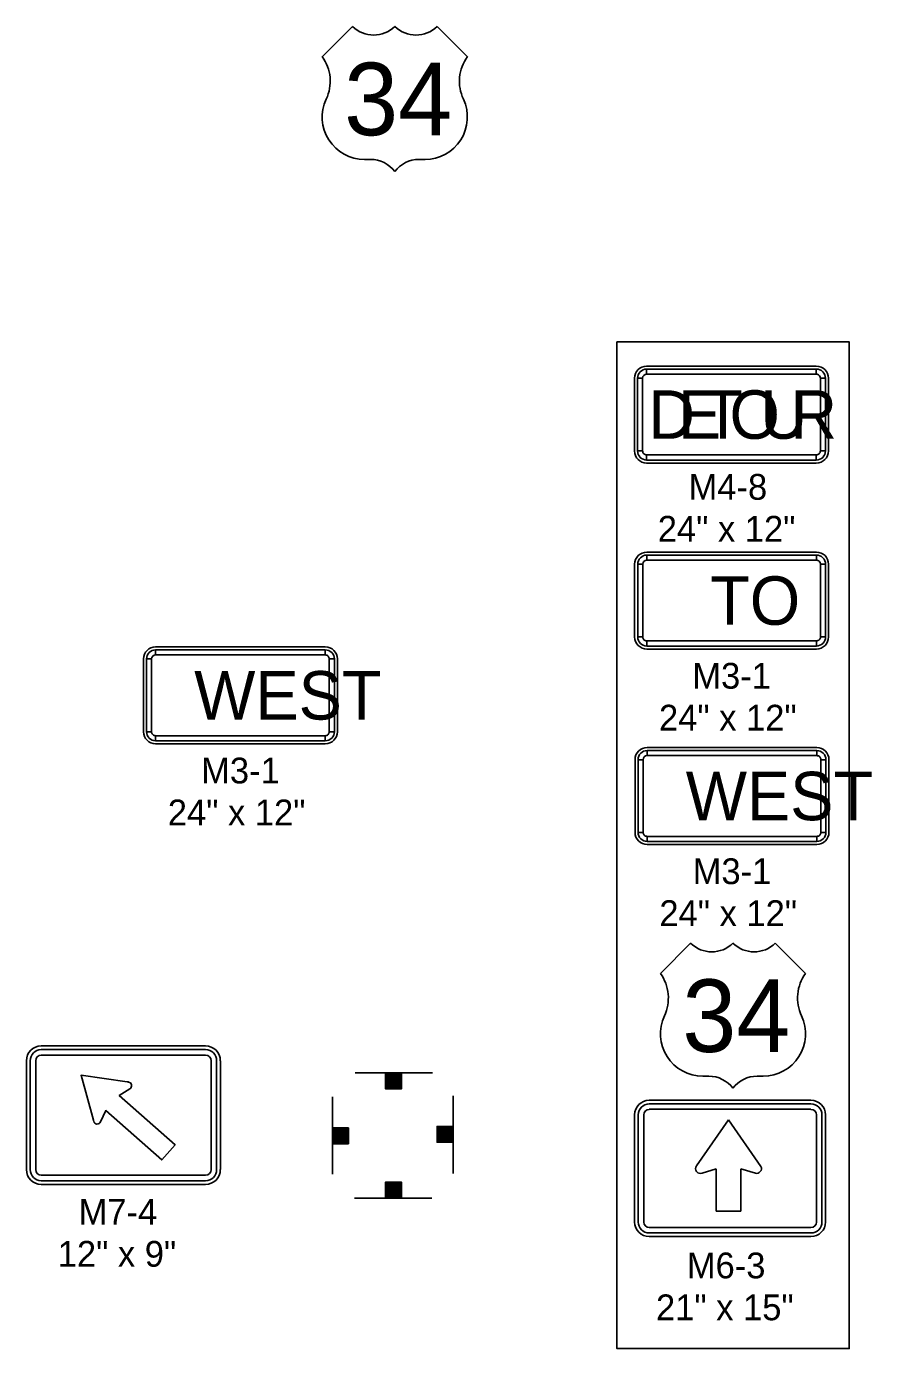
# Model space of a CAD drawing. Extents: x 10133 to 81668, y 6132 to 11018.
# Drawn here: x 11270.8 to 11532.9, y 6709.2 to 7119.3 of the extents above; entities that cross this region are included whole.
import ezdxf

# ---------------------------------------------------------------- set-up
doc = ezdxf.new("R2010")
doc.units = 0
for name, color, linetype in [('dsnTextFinalPlan', 7, 'Continuous'), ('Level 10', 7, 'Continuous'), ('Level 4', 7, 'Continuous'), ('Level 5', 7, 'Continuous')]:
    doc.layers.add(name, color=color, linetype=linetype)

msp = doc.modelspace()

# ---------------------------------------------------------------- linework, layer by layer
at = {"layer": 'dsnTextFinalPlan'}
for p, q in [((11326.33, 6803.08), (11275.37, 6803.08)), ((11270.79, 6798.5), (11270.79, 6764.72)), ((11330.92, 6764.72), (11330.92, 6798.5)), ((11372.68, 6794.77), (11396.68, 6794.77)), ((11387.04, 6794.41), (11382.16, 6794.41)), ((11382.16, 6794.16), (11387.04, 6794.16)), ((11387.04, 6793.94), (11382.16, 6793.94)), ((11382.16, 6793.71), (11387.04, 6793.71)), ((11387.04, 6793.51), (11382.16, 6793.51)), ((11382.16, 6793.33), (11387.04, 6793.33)), ((11387.04, 6793.04), (11382.16, 6793.04)), ((11382.16, 6792.81), (11387.04, 6792.81)), ((11387.04, 6792.61), (11382.16, 6792.63)), ((11382.16, 6792.33), (11387.04, 6792.33)), ((11387.04, 6792), (11382.16, 6792)), ((11382.16, 6791.63), (11387.04, 6791.63)), ((11387.04, 6791.43), (11382.16, 6791.45)), ((11382.16, 6791.07), (11387.04, 6791.06)), ((11387.04, 6790.87), (11382.16, 6790.87)), ((11365.65, 6763.31), (11365.65, 6787.31)), ((11382.16, 6790.6), (11387.04, 6790.6)), ((11387.04, 6790.4), (11382.16, 6790.4)), ((11382.16, 6790.12), (11387.04, 6790.12)), ((11403.13, 6787.57), (11403.13, 6763.57)), ((11366.01, 6777.66), (11366.01, 6772.79)), ((11366.25, 6772.79), (11366.25, 6777.66)), ((11366.48, 6777.66), (11366.48, 6772.79)), ((11366.71, 6772.79), (11366.71, 6777.66)), ((11366.91, 6777.66), (11366.91, 6772.79)), ((11367.09, 6772.79), (11367.09, 6777.66)), ((11367.38, 6777.66), (11367.38, 6772.79)), ((11367.61, 6772.79), (11367.61, 6777.66)), ((11367.81, 6777.66), (11367.79, 6772.79)), ((11368.09, 6772.79), (11368.09, 6777.66)), ((11368.41, 6777.66), (11368.41, 6772.79)), ((11368.79, 6772.79), (11368.79, 6777.66)), ((11368.99, 6777.66), (11368.97, 6772.79)), ((11369.35, 6772.79), (11369.36, 6777.66)), ((11369.54, 6777.66), (11369.54, 6772.79)), ((11369.82, 6772.79), (11369.82, 6777.66)), ((11370.02, 6777.66), (11370.02, 6772.79)), ((11370.29, 6772.79), (11370.29, 6777.66)), ((11398.48, 6778.09), (11398.48, 6773.22)), ((11398.76, 6773.22), (11398.76, 6778.09)), ((11398.95, 6778.09), (11398.95, 6773.22)), ((11399.23, 6773.22), (11399.23, 6778.09)), ((11399.43, 6778.09), (11399.41, 6773.22)), ((11399.79, 6773.22), (11399.81, 6778.09)), ((11399.99, 6778.09), (11399.99, 6773.22)), ((11400.36, 6773.22), (11400.36, 6778.09)), ((11400.69, 6778.09), (11400.69, 6773.22)), ((11400.97, 6773.22), (11400.98, 6778.09)), ((11401.16, 6778.09), (11401.16, 6773.22)), ((11401.39, 6773.22), (11401.39, 6778.09)), ((11401.69, 6778.09), (11401.69, 6773.22)), ((11401.87, 6773.22), (11401.87, 6778.09)), ((11402.06, 6778.09), (11402.06, 6773.22)), ((11402.29, 6773.22), (11402.29, 6778.09)), ((11402.52, 6778.09), (11402.52, 6773.22)), ((11402.77, 6773.22), (11402.77, 6778.09)), ((11275.37, 6760.13), (11326.33, 6760.13)), ((11387.02, 6760.54), (11382.14, 6760.54)), ((11382.14, 6760.26), (11387.02, 6760.26)), ((11387.02, 6760.06), (11382.14, 6760.06)), ((11382.14, 6759.78), (11387.02, 6759.78)), ((11387.02, 6759.59), (11382.14, 6759.6)), ((11382.14, 6759.23), (11387.02, 6759.21)), ((11387.02, 6759.03), (11382.14, 6759.03)), ((11382.14, 6758.65), (11387.02, 6758.65)), ((11387.02, 6758.33), (11382.14, 6758.33)), ((11382.14, 6758.05), (11387.02, 6758.03)), ((11396.5, 6755.89), (11372.5, 6755.89)), ((11387.02, 6757.85), (11382.14, 6757.85)), ((11382.14, 6757.62), (11387.02, 6757.62)), ((11387.02, 6757.33), (11382.14, 6757.33)), ((11382.14, 6757.15), (11387.02, 6757.15)), ((11387.02, 6756.95), (11382.14, 6756.95)), ((11382.14, 6756.72), (11387.02, 6756.72)), ((11387.02, 6756.49), (11382.14, 6756.49)), ((11382.14, 6756.25), (11387.02, 6756.25))]:
    msp.add_line(p, q, dxfattribs=at)
for points in [[(11453.89, 7021.45), (11525.96, 7021.45), (11525.96, 6709.23), (11453.89, 6709.23)], [(11387.04, 6794.69), (11382.13, 6794.69), (11382.13, 6789.78), (11387.04, 6789.78)], [(11365.73, 6777.66), (11365.73, 6772.75), (11370.64, 6772.75), (11370.64, 6777.66)], [(11403.05, 6773.22), (11403.05, 6778.13), (11398.14, 6778.13), (11398.14, 6773.22)], [(11382.14, 6755.97), (11387.05, 6755.97), (11387.05, 6760.88), (11382.14, 6760.88)]]:
    msp.add_lwpolyline(points, close=True, dxfattribs=at)
for points in [[(11302.07, 6791.95), (11287.71, 6794.02), (11291.56, 6780.04)], [(11293.78, 6779.52), (11295.4, 6783.04), (11312.73, 6767.75), (11316.88, 6772.46), (11299.56, 6787.75), (11302.85, 6789.78)]]:
    msp.add_lwpolyline(points, dxfattribs=at)
for centre, radius, start, end in [((11275.37, 6798.5), 4.58, 90, 180), ((11326.33, 6798.5), 4.58, 360, 90), ((11318.6, 6906.73), 115.96, 261.8049, 261.9654), ((11302.23, 6790.75), 1.16, 302.6073, 81.9654), ((11179.78, 6749.18), 115.96, 15.2659, 15.4333), ((11292.75, 6780.01), 1.14, 195.2659, 334.5454), ((11275.37, 6764.72), 4.58, 180, 270), ((11326.33, 6764.72), 4.58, 270, 0)]:
    msp.add_arc(centre, radius, start, end, dxfattribs=at)
at = {"layer": 'Level 10'}
for p, q in [((11463.1, 7013.94), (11515.72, 7013.94)), ((11463.1, 7011.44), (11463.1, 7013)), ((11515.72, 7013), (11515.72, 7011.44)), ((11459.34, 6987.64), (11459.34, 7010.19)), ((11460.28, 7010.19), (11461.85, 7010.19)), ((11516.97, 7010.19), (11518.53, 7010.19)), ((11519.47, 7010.19), (11519.47, 6987.64)), ((11461.85, 6987.64), (11460.28, 6987.64)), ((11518.53, 6987.64), (11516.97, 6987.64)), ((11463.1, 6984.82), (11463.1, 6986.39)), ((11515.72, 6983.88), (11463.1, 6983.88)), ((11515.72, 6986.39), (11515.72, 6984.82)), ((11463.15, 6956.26), (11515.76, 6956.26)), ((11463.15, 6953.75), (11463.15, 6955.32)), ((11515.76, 6955.32), (11515.76, 6953.75)), ((11459.39, 6929.95), (11459.39, 6952.5)), ((11460.33, 6952.5), (11461.9, 6952.5)), ((11517.01, 6952.5), (11518.58, 6952.5)), ((11519.52, 6952.5), (11519.52, 6929.95)), ((11310.84, 6926.87), (11363.45, 6926.87)), ((11461.9, 6929.95), (11460.33, 6929.95)), ((11463.15, 6927.13), (11463.15, 6928.7)), ((11515.76, 6926.19), (11463.15, 6926.19)), ((11515.76, 6928.7), (11515.76, 6927.13)), ((11518.58, 6929.95), (11517.01, 6929.95)), ((11307.08, 6900.56), (11307.08, 6923.11)), ((11308.02, 6923.11), (11309.58, 6923.11)), ((11310.84, 6924.36), (11310.84, 6925.93)), ((11363.45, 6925.93), (11363.45, 6924.36)), ((11364.7, 6923.11), (11366.27, 6923.11)), ((11367.21, 6923.11), (11367.21, 6900.56)), ((11309.58, 6900.56), (11308.02, 6900.56)), ((11310.84, 6897.74), (11310.84, 6899.31)), ((11363.45, 6899.31), (11363.45, 6897.74)), ((11366.27, 6900.56), (11364.7, 6900.56)), ((11363.45, 6896.8), (11310.84, 6896.8)), ((11463.27, 6895.64), (11515.88, 6895.64)), ((11463.27, 6893.14), (11463.27, 6894.7)), ((11515.88, 6894.7), (11515.88, 6893.14)), ((11459.51, 6869.33), (11459.51, 6891.88)), ((11460.45, 6891.88), (11462.01, 6891.88)), ((11517.13, 6891.88), (11518.7, 6891.88)), ((11519.64, 6891.88), (11519.64, 6869.33)), ((11462.01, 6869.33), (11460.45, 6869.33)), ((11518.7, 6869.33), (11517.13, 6869.33)), ((11463.27, 6866.52), (11463.27, 6868.08)), ((11515.88, 6865.58), (11463.27, 6865.58)), ((11515.88, 6868.08), (11515.88, 6866.52)), ((11326.33, 6801.94), (11275.37, 6801.94)), ((11326.33, 6800.22), (11275.37, 6800.22)), ((11271.93, 6798.5), (11271.93, 6764.72)), ((11273.65, 6798.5), (11273.65, 6764.72)), ((11328.05, 6764.72), (11328.05, 6798.5)), ((11329.77, 6764.72), (11329.77, 6798.5)), ((11514.06, 6786.24), (11463.89, 6786.24)), ((11463.9, 6785.12), (11514.07, 6785.12)), ((11463.9, 6783.43), (11514.07, 6783.43)), ((11459.38, 6781.73), (11459.38, 6748.48)), ((11460.52, 6748.48), (11460.52, 6781.73)), ((11462.21, 6748.48), (11462.21, 6781.73)), ((11488.46, 6780.16), (11478.55, 6765.89)), ((11498.56, 6765.72), (11488.46, 6780.16)), ((11515.76, 6781.73), (11515.76, 6748.48)), ((11517.45, 6781.73), (11517.45, 6748.48)), ((11518.57, 6748.48), (11518.57, 6781.73)), ((11275.37, 6763), (11326.33, 6763)), ((11480.29, 6763.63), (11484.64, 6765.02)), ((11484.64, 6765.02), (11484.64, 6751.97)), ((11492.29, 6764.85), (11492.29, 6765.02)), ((11492.29, 6765.02), (11496.82, 6763.63)), ((11492.29, 6751.8), (11492.29, 6764.85)), ((11275.37, 6761.28), (11326.33, 6761.28)), ((11484.64, 6751.97), (11484.64, 6751.8)), ((11484.64, 6751.8), (11492.29, 6751.8)), ((11514.07, 6746.78), (11463.9, 6746.78)), ((11463.89, 6743.97), (11514.06, 6743.97)), ((11514.07, 6745.09), (11463.9, 6745.09))]:
    msp.add_line(p, q, dxfattribs=at)
for points in [[(11515.72, 7013), (11463.1, 7013), (11463.1, 7011.44), (11515.72, 7011.44), (11515.72, 7013)], [(11460.28, 7010.19), (11460.28, 6987.64), (11461.85, 6987.64), (11461.85, 7010.19), (11460.28, 7010.19)], [(11518.53, 6987.64), (11518.53, 7010.19), (11516.97, 7010.19), (11516.97, 6987.64), (11518.53, 6987.64)], [(11463.1, 6984.82), (11515.72, 6984.82), (11515.72, 6986.39), (11463.1, 6986.39), (11463.1, 6984.82)], [(11515.76, 6955.32), (11463.15, 6955.32), (11463.15, 6953.75), (11515.76, 6953.75), (11515.76, 6955.32)], [(11460.33, 6952.5), (11460.33, 6929.95), (11461.9, 6929.95), (11461.9, 6952.5), (11460.33, 6952.5)], [(11518.58, 6929.95), (11518.58, 6952.5), (11517.01, 6952.5), (11517.01, 6929.95), (11518.58, 6929.95)], [(11463.15, 6927.13), (11515.76, 6927.13), (11515.76, 6928.7), (11463.15, 6928.7), (11463.15, 6927.13)], [(11308.02, 6923.11), (11308.02, 6900.56), (11309.58, 6900.56), (11309.58, 6923.11), (11308.02, 6923.11)], [(11363.45, 6925.93), (11310.84, 6925.93), (11310.84, 6924.36), (11363.45, 6924.36), (11363.45, 6925.93)], [(11366.27, 6900.56), (11366.27, 6923.11), (11364.7, 6923.11), (11364.7, 6900.56), (11366.27, 6900.56)], [(11310.84, 6897.74), (11363.45, 6897.74), (11363.45, 6899.31), (11310.84, 6899.31), (11310.84, 6897.74)], [(11515.88, 6894.7), (11463.27, 6894.7), (11463.27, 6893.14), (11515.88, 6893.14), (11515.88, 6894.7)], [(11460.45, 6891.88), (11460.45, 6869.33), (11462.01, 6869.33), (11462.01, 6891.88), (11460.45, 6891.88)], [(11518.7, 6869.33), (11518.7, 6891.88), (11517.13, 6891.88), (11517.13, 6869.33), (11518.7, 6869.33)], [(11463.27, 6866.52), (11515.88, 6866.52), (11515.88, 6868.08), (11463.27, 6868.08), (11463.27, 6866.52)]]:
    msp.add_lwpolyline(points, close=True, dxfattribs=at)
for centre, radius, start, end in [((11463.1, 7010.19), 3.76, 90, 180), ((11463.1, 7010.19), 2.82, 90.0002, 179.9998), ((11515.72, 7010.19), 3.76, 0, 90), ((11515.72, 7010.19), 2.82, 0, 90.0002), ((11463.1, 7010.19), 1.25, 90.0002, 179.9998), ((11515.72, 7010.19), 1.25, 0, 90.0002), ((11463.1, 6987.64), 3.76, 180, 270), ((11463.1, 6987.64), 2.82, 179.9998, 270.0001), ((11463.1, 6987.64), 1.25, 179.9998, 270.0001), ((11515.72, 6987.64), 2.82, 270.0001, 0.0003), ((11515.72, 6987.64), 1.25, 270.0001, 0.0003), ((11515.72, 6987.64), 3.76, 270, 359.9911), ((11463.15, 6952.5), 3.76, 90, 180), ((11463.15, 6952.5), 2.82, 90.0002, 179.9998), ((11515.76, 6952.5), 3.76, 0, 90), ((11515.76, 6952.5), 2.82, 0, 90.0002), ((11463.15, 6952.5), 1.25, 90.0002, 179.9998), ((11515.76, 6952.5), 1.25, 0, 90.0002), ((11310.84, 6923.11), 3.76, 90, 180), ((11363.45, 6923.11), 3.76, 0, 90), ((11463.15, 6929.95), 3.76, 180, 270), ((11463.15, 6929.95), 2.82, 179.9998, 270.0001), ((11463.15, 6929.95), 1.25, 179.9998, 270.0001), ((11515.76, 6929.95), 2.82, 270.0001, 0.0003), ((11515.76, 6929.95), 1.25, 270.0001, 0.0003), ((11515.76, 6929.95), 3.76, 270, 359.9911), ((11310.84, 6923.11), 2.82, 90.0002, 179.9998), ((11310.84, 6923.11), 1.25, 90.0002, 179.9998), ((11363.45, 6923.11), 2.82, 0, 90.0002), ((11363.45, 6923.11), 1.25, 0, 90.0002), ((11310.84, 6900.56), 3.76, 180, 270), ((11310.84, 6900.56), 2.82, 179.9998, 270.0001), ((11310.84, 6900.56), 1.25, 179.9998, 270.0001), ((11363.45, 6900.56), 2.82, 270.0001, 0.0003), ((11363.45, 6900.56), 1.25, 270.0001, 0.0003), ((11363.45, 6900.56), 3.76, 270, 359.9911), ((11463.27, 6891.88), 3.76, 90, 180), ((11463.27, 6891.88), 2.82, 90.0002, 179.9998), ((11515.88, 6891.88), 3.76, 0, 90), ((11515.88, 6891.88), 2.82, 0, 90.0002), ((11463.27, 6891.88), 1.25, 90.0002, 179.9998), ((11515.88, 6891.88), 1.25, 0, 90.0002), ((11463.27, 6869.33), 3.76, 180, 270), ((11463.27, 6869.33), 2.82, 179.9998, 270.0001), ((11463.27, 6869.33), 1.25, 179.9998, 270.0001), ((11515.88, 6869.33), 2.82, 270.0001, 0.0003), ((11515.88, 6869.33), 1.25, 270.0001, 0.0003), ((11515.88, 6869.33), 3.76, 270, 359.9911), ((11275.37, 6798.5), 3.44, 90, 180), ((11275.37, 6798.5), 1.72, 90, 180), ((11326.33, 6798.5), 3.44, 0, 90), ((11326.33, 6798.5), 1.72, 0, 90), ((11463.89, 6781.73), 4.51, 90, 180), ((11463.9, 6781.73), 3.38, 90, 180), ((11463.9, 6781.73), 1.69, 90, 180), ((11514.06, 6781.73), 4.51, 360, 90), ((11514.07, 6781.73), 3.38, 0, 90), ((11514.07, 6781.73), 1.69, 0, 90), ((11275.37, 6764.72), 3.44, 180, 270), ((11275.37, 6764.72), 1.72, 180, 270), ((11326.33, 6764.72), 3.44, 270, 360), ((11326.33, 6764.72), 1.72, 270, 0), ((11479.76, 6765.02), 1.49, 144.2678, 290.8693), ((11497.2, 6765.07), 1.5, 254.9696, 25.4193), ((11463.89, 6748.48), 4.51, 180, 270), ((11463.9, 6748.48), 3.38, 180, 270), ((11463.9, 6748.48), 1.69, 180, 270), ((11514.06, 6748.48), 4.51, 270, 0), ((11514.07, 6748.48), 3.38, 270, 0), ((11514.07, 6748.48), 1.69, 270, 0)]:
    msp.add_arc(centre, radius, start, end, dxfattribs=at)
at = {"layer": 'Level 4'}
for p, q in [((11371.89, 7119.3), (11362.51, 7109.92)), ((11407.51, 7109.92), (11398.14, 7119.3)), ((11375.64, 7078.05), (11377.51, 7078.05)), ((11392.51, 7078.05), (11394.39, 7078.05)), ((11476.75, 6834.97), (11467.37, 6825.59)), ((11512.37, 6825.59), (11503, 6834.97)), ((11480.5, 6793.72), (11482.37, 6793.72)), ((11497.37, 6793.72), (11499.25, 6793.72))]:
    msp.add_line(p, q, dxfattribs=at)
for centre, radius, start, end in [((11378.45, 7125.99), 9.38, 225.5729, 314.4272), ((11391.58, 7125.99), 9.38, 225.5729, 314.4272), ((11351.85, 7102.27), 13.13, 334.9895, 35.6629), ((11418.18, 7102.27), 13.13, 144.3372, 205.01), ((11375.64, 7091.17), 13.13, 154.9897, 270.0001), ((11394.39, 7091.17), 13.13, 270.0001, 25.0104), ((11377.51, 7068.67), 9.38, 36.8699, 90.0002), ((11392.51, 7068.67), 9.38, 90.0002, 143.13), ((11483.31, 6841.66), 9.38, 225.5729, 314.4272), ((11496.44, 6841.66), 9.38, 225.5729, 314.4272), ((11456.71, 6817.94), 13.13, 334.9895, 35.6629), ((11523.04, 6817.94), 13.13, 144.3372, 205.01), ((11480.5, 6806.84), 13.13, 154.9897, 270.0001), ((11499.25, 6806.84), 13.13, 270.0001, 25.0104), ((11482.37, 6784.34), 9.38, 36.8699, 90.0002), ((11497.37, 6784.34), 9.38, 90.0002, 143.13)]:
    msp.add_arc(centre, radius, start, end, dxfattribs=at)

# ---------------------------------------------------------------- texts
at = {"layer": 'Level 10'}
for s, height, p in [('D', 15.03, (11463.59, 6991.4)), ('E', 15.03, (11472.83, 6991.4)), ('T', 15.03, (11480.61, 6991.4)), ('O', 15.03, (11488.81, 6991.4)), ('U', 15.03, (11498.4, 6991.4)), ('R', 15.03, (11507.64, 6991.4)), ('TO', 15.032, (11482.81, 6933.71)), ('WEST', 15.032, (11322.81, 6904.32)), ('WEST', 15.032, (11475.24, 6873.09))]:
    msp.add_text(s, height=height, dxfattribs=at).set_placement(p)
at = {"layer": 'Level 4'}
for p in [(11369.31, 7085.55), (11474.17, 6801.22)]:
    msp.add_text('34', height=22.5, dxfattribs=at).set_placement(p)
at = {"layer": 'Level 5'}
for s, p in [('M4-8', (11476.11, 6972.49)), ('24" x 12"', (11466.56, 6959.49)), ('M3-1', (11477.27, 6913.9)), ('24" x 12"', (11466.94, 6900.9)), ('M3-1', (11324.96, 6884.51)), ('24" x 12"', (11314.63, 6871.51)), ('M3-1', (11477.39, 6853.28)), ('24" x 12"', (11467.06, 6840.28)), ('M7-4', (11286.96, 6747.62)), ('12" x 9"', (11280.49, 6734.62)), ('M6-3', (11475.57, 6731.01)), ('21" x 15"', (11466.01, 6718.01))]:
    msp.add_text(s, height=8, dxfattribs=at).set_placement(p)

doc.saveas('drawing.dxf')
